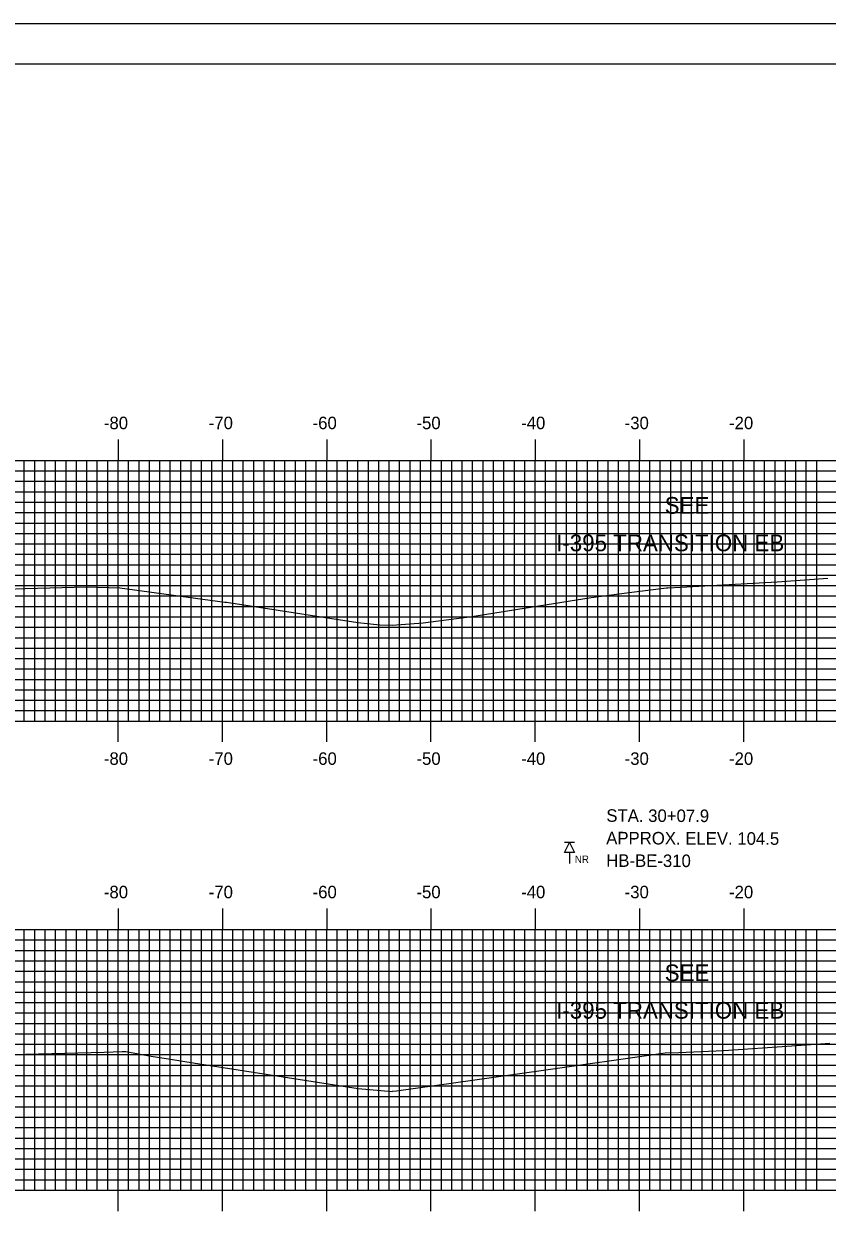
# Model space of a CAD drawing. Extents: x 841782 to 842125, y 363538 to 363758.
# Drawn here: x 841858.3 to 841935.4, y 363643.2 to 363757.6 of the extents above; entities that cross this region are included whole.
import ezdxf

# ---------------------------------------------------------------- set-up
doc = ezdxf.new("R2010")
doc.units = 0
for name, color, linetype in [('ANNOTATION', 7, 'Continuous'), ('BORDER', 7, 'Continuous'), ('BORING - NO REFUSAL', 7, 'Continuous'), ('H_V ANNOTATION', 7, 'Continuous'), ('MAJOR', 7, 'Continuous'), ('MINOR', 7, 'Continuous'), ('PLOT BOUNDARY', 7, 'Continuous'), ('S_Roadway_Centerline', 7, 'Continuous')]:
    doc.layers.add(name, color=color, linetype=linetype)

msp = doc.modelspace()

# ---------------------------------------------------------------- linework, layer by layer
at = {"layer": 'BORDER'}
msp.add_lwpolyline([(841797.77, 363543.72), (842117.77, 363543.72), (842117.77, 363753.72), (841797.77, 363753.72)], close=True, dxfattribs=at)
at = {"layer": 'BORING - NO REFUSAL'}
for p, q in [((841911.15, 363679.08), (841910.19, 363679.08)), ((841910.67, 363678.12), (841910.67, 363677.06))]:
    msp.add_line(p, q, dxfattribs=at)
msp.add_lwpolyline([(841910.67, 363679.08), (841911.15, 363678.12), (841910.19, 363678.12)], close=True, dxfattribs=at)
at = {"layer": 'MAJOR'}
for p, q in [((841867.37, 363717.73), (841867.37, 363715.72)), ((841877.37, 363717.73), (841877.37, 363715.72)), ((841887.37, 363717.73), (841887.37, 363715.72)), ((841897.37, 363717.73), (841897.37, 363715.72)), ((841907.37, 363717.73), (841907.37, 363715.72)), ((841917.37, 363717.73), (841917.37, 363715.72)), ((841927.37, 363717.73), (841927.37, 363715.72)), ((841807.37, 363715.72), (842087.37, 363715.72)), ((841807.37, 363715.72), (842087.37, 363715.72)), ((841867.37, 363690.72), (841867.37, 363715.72)), ((841877.37, 363690.72), (841877.37, 363715.72)), ((841887.37, 363690.72), (841887.37, 363715.72)), ((841897.37, 363690.72), (841897.37, 363715.72)), ((841907.37, 363690.72), (841907.37, 363715.72)), ((841917.37, 363690.72), (841917.37, 363715.72)), ((841927.37, 363690.72), (841927.37, 363715.72)), ((841807.37, 363710.72), (842087.37, 363710.72)), ((841807.37, 363705.72), (842087.37, 363705.72)), ((841807.37, 363700.72), (842087.37, 363700.72)), ((841807.37, 363695.72), (842087.37, 363695.72)), ((841807.37, 363690.72), (842087.37, 363690.72)), ((841807.37, 363690.72), (842087.37, 363690.72)), ((841867.37, 363688.72), (841867.37, 363690.72)), ((841877.37, 363688.72), (841877.37, 363690.72)), ((841887.37, 363688.72), (841887.37, 363690.72)), ((841897.37, 363688.72), (841897.37, 363690.72)), ((841907.37, 363688.72), (841907.37, 363690.72)), ((841917.37, 363688.72), (841917.37, 363690.72)), ((841927.37, 363688.72), (841927.37, 363690.72)), ((841867.37, 363672.73), (841867.37, 363670.72)), ((841877.37, 363672.73), (841877.37, 363670.72)), ((841887.37, 363672.73), (841887.37, 363670.72)), ((841897.37, 363672.73), (841897.37, 363670.72)), ((841907.37, 363672.73), (841907.37, 363670.72)), ((841917.37, 363672.73), (841917.37, 363670.72)), ((841927.37, 363672.73), (841927.37, 363670.72)), ((841807.37, 363670.72), (842087.37, 363670.72)), ((841807.37, 363670.72), (842087.37, 363670.72)), ((841867.37, 363645.72), (841867.37, 363670.72)), ((841877.37, 363645.72), (841877.37, 363670.72)), ((841887.37, 363645.72), (841887.37, 363670.72)), ((841897.37, 363645.72), (841897.37, 363670.72)), ((841907.37, 363645.72), (841907.37, 363670.72)), ((841917.37, 363645.72), (841917.37, 363670.72)), ((841927.37, 363645.72), (841927.37, 363670.72)), ((841807.37, 363665.72), (842087.37, 363665.72)), ((841807.37, 363660.72), (842087.37, 363660.72)), ((841807.37, 363655.72), (842087.37, 363655.72)), ((841807.37, 363650.72), (842087.37, 363650.72)), ((841807.37, 363645.72), (842087.37, 363645.72)), ((841807.37, 363645.72), (842087.37, 363645.72)), ((841867.37, 363643.72), (841867.37, 363645.72)), ((841877.37, 363643.72), (841877.37, 363645.72)), ((841887.37, 363643.72), (841887.37, 363645.72)), ((841897.37, 363643.72), (841897.37, 363645.72)), ((841907.37, 363643.72), (841907.37, 363645.72)), ((841917.37, 363643.72), (841917.37, 363645.72)), ((841927.37, 363643.72), (841927.37, 363645.72))]:
    msp.add_line(p, q, dxfattribs=at)
at = {"layer": 'MINOR'}
for p, q in [((841858.37, 363690.72), (841858.37, 363715.72)), ((841859.37, 363690.72), (841859.37, 363715.72)), ((841860.37, 363690.72), (841860.37, 363715.72)), ((841861.37, 363690.72), (841861.37, 363715.72)), ((841862.37, 363690.72), (841862.37, 363715.72)), ((841863.37, 363690.72), (841863.37, 363715.72)), ((841864.37, 363690.72), (841864.37, 363715.72)), ((841865.37, 363690.72), (841865.37, 363715.72)), ((841866.37, 363690.72), (841866.37, 363715.72)), ((841868.37, 363690.72), (841868.37, 363715.72)), ((841869.37, 363690.72), (841869.37, 363715.72)), ((841870.37, 363690.72), (841870.37, 363715.72)), ((841871.37, 363690.72), (841871.37, 363715.72)), ((841872.37, 363690.72), (841872.37, 363715.72)), ((841873.37, 363690.72), (841873.37, 363715.72)), ((841874.37, 363690.72), (841874.37, 363715.72)), ((841875.37, 363690.72), (841875.37, 363715.72)), ((841876.37, 363690.72), (841876.37, 363715.72)), ((841878.37, 363690.72), (841878.37, 363715.72)), ((841879.37, 363690.72), (841879.37, 363715.72)), ((841880.37, 363690.72), (841880.37, 363715.72)), ((841881.37, 363690.72), (841881.37, 363715.72)), ((841882.37, 363690.72), (841882.37, 363715.72)), ((841883.37, 363690.72), (841883.37, 363715.72)), ((841884.37, 363690.72), (841884.37, 363715.72)), ((841885.37, 363690.72), (841885.37, 363715.72)), ((841886.37, 363690.72), (841886.37, 363715.72)), ((841888.37, 363690.72), (841888.37, 363715.72)), ((841889.37, 363690.72), (841889.37, 363715.72)), ((841890.37, 363690.72), (841890.37, 363715.72)), ((841891.37, 363690.72), (841891.37, 363715.72)), ((841892.37, 363690.72), (841892.37, 363715.72)), ((841893.37, 363690.72), (841893.37, 363715.72)), ((841894.37, 363690.72), (841894.37, 363715.72)), ((841895.37, 363690.72), (841895.37, 363715.72)), ((841896.37, 363690.72), (841896.37, 363715.72)), ((841898.37, 363690.72), (841898.37, 363715.72)), ((841899.37, 363690.72), (841899.37, 363715.72)), ((841900.37, 363690.72), (841900.37, 363715.72)), ((841901.37, 363690.72), (841901.37, 363715.72)), ((841902.37, 363690.72), (841902.37, 363715.72)), ((841903.37, 363690.72), (841903.37, 363715.72)), ((841904.37, 363690.72), (841904.37, 363715.72)), ((841905.37, 363690.72), (841905.37, 363715.72)), ((841906.37, 363690.72), (841906.37, 363715.72)), ((841908.37, 363690.72), (841908.37, 363715.72)), ((841909.37, 363690.72), (841909.37, 363715.72)), ((841910.37, 363690.72), (841910.37, 363715.72)), ((841911.37, 363690.72), (841911.37, 363715.72)), ((841912.37, 363690.72), (841912.37, 363715.72)), ((841913.37, 363690.72), (841913.37, 363715.72)), ((841914.37, 363690.72), (841914.37, 363715.72)), ((841915.37, 363690.72), (841915.37, 363715.72)), ((841916.37, 363690.72), (841916.37, 363715.72)), ((841918.37, 363690.72), (841918.37, 363715.72)), ((841919.37, 363690.72), (841919.37, 363715.72)), ((841920.37, 363690.72), (841920.37, 363715.72)), ((841921.37, 363690.72), (841921.37, 363715.72)), ((841922.37, 363690.72), (841922.37, 363715.72)), ((841923.37, 363690.72), (841923.37, 363715.72)), ((841924.37, 363690.72), (841924.37, 363715.72)), ((841925.37, 363690.72), (841925.37, 363715.72)), ((841926.37, 363690.72), (841926.37, 363715.72)), ((841928.37, 363690.72), (841928.37, 363715.72)), ((841929.37, 363690.72), (841929.37, 363715.72)), ((841930.37, 363690.72), (841930.37, 363715.72)), ((841931.37, 363690.72), (841931.37, 363715.72)), ((841932.37, 363690.72), (841932.37, 363715.72)), ((841933.37, 363690.72), (841933.37, 363715.72)), ((841934.37, 363690.72), (841934.37, 363715.72)), ((841807.37, 363714.72), (842087.37, 363714.72)), ((841807.37, 363713.72), (842087.37, 363713.72)), ((841807.37, 363712.72), (842087.37, 363712.72)), ((841807.37, 363711.72), (842087.37, 363711.72)), ((841807.37, 363709.72), (842087.37, 363709.72)), ((841807.37, 363708.72), (842087.37, 363708.72)), ((841807.37, 363707.72), (842087.37, 363707.72)), ((841807.37, 363706.72), (842087.37, 363706.72)), ((841807.37, 363704.72), (842087.37, 363704.72)), ((841807.37, 363703.72), (842087.37, 363703.72)), ((841807.37, 363702.72), (842087.37, 363702.72)), ((841807.37, 363701.72), (842087.37, 363701.72)), ((841807.37, 363699.72), (842087.37, 363699.72)), ((841807.37, 363698.72), (842087.37, 363698.72)), ((841807.37, 363697.72), (842087.37, 363697.72)), ((841807.37, 363696.72), (842087.37, 363696.72)), ((841807.37, 363694.72), (842087.37, 363694.72)), ((841807.37, 363693.72), (842087.37, 363693.72)), ((841807.37, 363692.72), (842087.37, 363692.72)), ((841807.37, 363691.72), (842087.37, 363691.72)), ((841858.37, 363645.72), (841858.37, 363670.72)), ((841859.37, 363645.72), (841859.37, 363670.72)), ((841860.37, 363645.72), (841860.37, 363670.72)), ((841861.37, 363645.72), (841861.37, 363670.72)), ((841862.37, 363645.72), (841862.37, 363670.72)), ((841863.37, 363645.72), (841863.37, 363670.72)), ((841864.37, 363645.72), (841864.37, 363670.72)), ((841865.37, 363645.72), (841865.37, 363670.72)), ((841866.37, 363645.72), (841866.37, 363670.72)), ((841868.37, 363645.72), (841868.37, 363670.72)), ((841869.37, 363645.72), (841869.37, 363670.72)), ((841870.37, 363645.72), (841870.37, 363670.72)), ((841871.37, 363645.72), (841871.37, 363670.72)), ((841872.37, 363645.72), (841872.37, 363670.72)), ((841873.37, 363645.72), (841873.37, 363670.72)), ((841874.37, 363645.72), (841874.37, 363670.72)), ((841875.37, 363645.72), (841875.37, 363670.72)), ((841876.37, 363645.72), (841876.37, 363670.72)), ((841878.37, 363645.72), (841878.37, 363670.72)), ((841879.37, 363645.72), (841879.37, 363670.72)), ((841880.37, 363645.72), (841880.37, 363670.72)), ((841881.37, 363645.72), (841881.37, 363670.72)), ((841882.37, 363645.72), (841882.37, 363670.72)), ((841883.37, 363645.72), (841883.37, 363670.72)), ((841884.37, 363645.72), (841884.37, 363670.72)), ((841885.37, 363645.72), (841885.37, 363670.72)), ((841886.37, 363645.72), (841886.37, 363670.72)), ((841888.37, 363645.72), (841888.37, 363670.72)), ((841889.37, 363645.72), (841889.37, 363670.72)), ((841890.37, 363645.72), (841890.37, 363670.72)), ((841891.37, 363645.72), (841891.37, 363670.72)), ((841892.37, 363645.72), (841892.37, 363670.72)), ((841893.37, 363645.72), (841893.37, 363670.72)), ((841894.37, 363645.72), (841894.37, 363670.72)), ((841895.37, 363645.72), (841895.37, 363670.72)), ((841896.37, 363645.72), (841896.37, 363670.72)), ((841898.37, 363645.72), (841898.37, 363670.72)), ((841899.37, 363645.72), (841899.37, 363670.72)), ((841900.37, 363645.72), (841900.37, 363670.72)), ((841901.37, 363645.72), (841901.37, 363670.72)), ((841902.37, 363645.72), (841902.37, 363670.72)), ((841903.37, 363645.72), (841903.37, 363670.72)), ((841904.37, 363645.72), (841904.37, 363670.72)), ((841905.37, 363645.72), (841905.37, 363670.72)), ((841906.37, 363645.72), (841906.37, 363670.72)), ((841908.37, 363645.72), (841908.37, 363670.72)), ((841909.37, 363645.72), (841909.37, 363670.72)), ((841910.37, 363645.72), (841910.37, 363670.72)), ((841911.37, 363645.72), (841911.37, 363670.72)), ((841912.37, 363645.72), (841912.37, 363670.72)), ((841913.37, 363645.72), (841913.37, 363670.72)), ((841914.37, 363645.72), (841914.37, 363670.72)), ((841915.37, 363645.72), (841915.37, 363670.72)), ((841916.37, 363645.72), (841916.37, 363670.72)), ((841918.37, 363645.72), (841918.37, 363670.72)), ((841919.37, 363645.72), (841919.37, 363670.72)), ((841920.37, 363645.72), (841920.37, 363670.72)), ((841921.37, 363645.72), (841921.37, 363670.72)), ((841922.37, 363645.72), (841922.37, 363670.72)), ((841923.37, 363645.72), (841923.37, 363670.72)), ((841924.37, 363645.72), (841924.37, 363670.72)), ((841925.37, 363645.72), (841925.37, 363670.72)), ((841926.37, 363645.72), (841926.37, 363670.72)), ((841928.37, 363645.72), (841928.37, 363670.72)), ((841929.37, 363645.72), (841929.37, 363670.72)), ((841930.37, 363645.72), (841930.37, 363670.72)), ((841931.37, 363645.72), (841931.37, 363670.72)), ((841932.37, 363645.72), (841932.37, 363670.72)), ((841933.37, 363645.72), (841933.37, 363670.72)), ((841934.37, 363645.72), (841934.37, 363670.72)), ((841807.37, 363669.72), (842087.37, 363669.72)), ((841807.37, 363668.72), (842087.37, 363668.72)), ((841807.37, 363667.72), (842087.37, 363667.72)), ((841807.37, 363666.72), (842087.37, 363666.72)), ((841807.37, 363664.72), (842087.37, 363664.72)), ((841807.37, 363663.72), (842087.37, 363663.72)), ((841807.37, 363662.72), (842087.37, 363662.72)), ((841807.37, 363661.72), (842087.37, 363661.72)), ((841807.37, 363659.72), (842087.37, 363659.72)), ((841807.37, 363658.72), (842087.37, 363658.72)), ((841807.37, 363657.72), (842087.37, 363657.72)), ((841807.37, 363656.72), (842087.37, 363656.72)), ((841807.37, 363654.72), (842087.37, 363654.72)), ((841807.37, 363653.72), (842087.37, 363653.72)), ((841807.37, 363652.72), (842087.37, 363652.72)), ((841807.37, 363651.72), (842087.37, 363651.72)), ((841807.37, 363649.72), (842087.37, 363649.72)), ((841807.37, 363648.72), (842087.37, 363648.72)), ((841807.37, 363647.72), (842087.37, 363647.72)), ((841807.37, 363646.72), (842087.37, 363646.72))]:
    msp.add_line(p, q, dxfattribs=at)
at = {"layer": 'PLOT BOUNDARY'}
msp.add_lwpolyline([(841781.59, 363537.6), (842121.59, 363537.6), (842121.59, 363757.6), (841781.59, 363757.6)], close=True, dxfattribs=at)
at = {"layer": 'S_Roadway_Centerline'}
for points in [[(841852.94, 363703.23), (841858.46, 363703.44), (841864.32, 363703.59), (841867.53, 363703.5), (841877.59, 363702.14), (841877.76, 363702.12), (841880.04, 363701.78), (841890.35, 363700.16), (841892.46, 363699.96), (841893.64, 363699.93), (841896.62, 363700.14), (841901.3, 363700.75), (841912.74, 363702.56), (841916.89, 363703.11), (841919.97, 363703.51), (841920.08, 363703.5), (841921.33, 363703.58), (841930.58, 363704.09), (841935.44, 363704.42)], [(841854.67, 363658.68), (841866.02, 363658.96), (841867.76, 363659.01), (841868.11, 363659.01), (841870.55, 363658.59), (841872.38, 363658.28), (841874.56, 363657.95), (841890.4, 363655.48), (841893.65, 363655.18), (841893.68, 363655.21), (841894.07, 363655.24), (841903.4, 363656.57), (841906.56, 363657.02), (841907.72, 363657.18), (841919.84, 363658.9), (841921.16, 363658.93), (841925.42, 363659.13), (841931.97, 363659.56), (841935.64, 363659.83)]]:
    msp.add_lwpolyline(points, dxfattribs=at)

# ---------------------------------------------------------------- texts
at = {"layer": 'ANNOTATION'}
for s, p in [('SEE', (841919.79, 363710.61)), ('I-395 TRANSITION EB', (841909.38, 363707.01)), ('SEE', (841919.79, 363665.77)), ('I-395 TRANSITION EB', (841909.38, 363662.17))]:
    msp.add_text(s, height=1.6, dxfattribs=at).set_placement(p)
at = {"layer": 'BORING - NO REFUSAL'}
for s, p in [('STA. 30+07.9', (841914.19, 363681.06)), ('APPROX. ELEV. 104.5', (841914.18, 363678.9)), ('HB-BE-310', (841914.18, 363676.74))]:
    msp.add_text(s, height=1.2, rotation=359.8142, dxfattribs=at).set_placement(p)
msp.add_text('NR', height=0.7, dxfattribs=at).set_placement((841911.17, 363677.11))
at = {"layer": 'H_V ANNOTATION'}
for s, p in [('-80', (841866, 363718.72)), ('-70', (841876.06, 363718.72)), ('-60', (841886.02, 363718.72)), ('-50', (841895.98, 363718.72)), ('-40', (841906.02, 363718.72)), ('-30', (841915.95, 363718.72)), ('-20', (841925.96, 363718.72)), ('-80', (841866, 363686.52)), ('-70', (841876.06, 363686.52)), ('-60', (841886.02, 363686.52)), ('-50', (841895.98, 363686.52)), ('-40', (841906.02, 363686.52)), ('-30', (841915.95, 363686.52)), ('-20', (841925.96, 363686.52)), ('-80', (841866, 363673.72)), ('-70', (841876.06, 363673.72)), ('-60', (841886.02, 363673.72)), ('-50', (841895.98, 363673.72)), ('-40', (841906.02, 363673.72)), ('-30', (841915.95, 363673.72)), ('-20', (841925.96, 363673.72))]:
    msp.add_text(s, height=1.2, dxfattribs=at).set_placement(p)

doc.saveas('drawing.dxf')
